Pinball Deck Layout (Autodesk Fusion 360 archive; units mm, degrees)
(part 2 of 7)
sketch "Reload Launch Plunger" plane through (0, 0, 8) normal (0, 0, 1) x axis (-1, 0, 0)
  line L1 (-360.8217, -46.399) -> (-358.0535, -46.4059)
  line L2 (-363.9178, -46.3914) -> (-361.0138, -46.3986)
  line L3 (-361.0035, -43.4046) -> (-362.4727, -43.3979)
  line L4 (-358.0433, -43.4179) -> (-360.8112, -43.4054)
  line L5 (-360.8495, -54.399) -> (-358.0816, -54.4058)
  line L6 (-363.9457, -54.3914) -> (-361.0418, -54.3985)
  line L7 (-361.0313, -51.4045) -> (-363.9352, -51.3914)
  line L8 (-358.071, -51.4179) -> (-360.8392, -51.4054)
  line L9 (-337.909, -43.4822) -> (-343.909, -43.4612)
  line L10 (-340.8631, -46.4708) -> (-337.92, -46.4822)
  line L11 (-343.8396, -46.4594) -> (-340.9768, -46.4704)
  line L12 (-343.9473, -54.4612) -> (-337.9474, -54.4821)
  line L13 (-341.0041, -51.4729) -> (-343.9361, -51.4612)
  line L14 (-338.0323, -51.4848) -> (-340.8681, -51.4735)
  line L15 (-332.4666, -38.0012) -> (-332.3898, -38.0014)
  line L16 (-332.4666, -35.9861) -> (-332.4666, -38.0012)
  line L17 (-369.4666, -35.9861) -> (-332.4666, -35.9861)
  line L18 (-369.4666, -62.0013) -> (-369.4666, -35.9861)
  line L19 (-332.4666, -62.0013) -> (-369.4666, -62.0013)
  line L20 (-332.4666, -60.0013) -> (-332.4666, -62.0013)
  line L21 (-332.3898, -38.0014) -> (-332.4666, -60.0013)
  line L22 (-369.5336, -53.1093) -> (-390.5336, -53.1093)
  line L23 (-390.5336, -45.1093) -> (-369.5336, -45.1093)
  line L24 (-371.5336, -45.1093) -> (-390.5336, -45.1093)
  line L25 (-384.5336, -45.1093) -> (-384.5336, -53.1093)
  line L26 (-387.5336, -45.1093) -> (-387.5336, -53.1093)
  line L27 (-371.5336, -45.1093) -> (-371.5336, -53.1093)
  line L28 (-384.5336, -45.1093) -> (-384.5336, -53.1093)
  line L29 (-390.5336, -53.1093) -> (-390.5336, -45.1093)
  line L30 (-369.5336, -45.1093) -> (-369.5336, -53.1093)
  line L31 (-371.5336, -53.1093) -> (-390.5336, -53.1093)
  line L32 (-332.4666, -35.9861) -> (-332.4666, -38.0012)
  line L33 (-361.0035, -43.4046) -> (-362.68, -43.397)
  line L34 (-332.4666, -38.0012) -> (-332.3898, -38.0014)
  line L35 (-358.071, -51.4179) -> (-360.8392, -51.4054)
  line L36 (-338.0323, -51.4848) -> (-340.8681, -51.4735)
  line L37 (-361.0313, -51.4045) -> (-363.9352, -51.3914)
  line L38 (-387.5336, -45.1093) -> (-387.5336, -53.1093)
  line L39 (-369.5336, -53.1093) -> (-390.5336, -53.1093)
  line L40 (-390.5336, -53.1093) -> (-390.5336, -45.1093)
  line L41 (-360.8217, -46.399) -> (-358.0535, -46.4059)
  line L42 (-337.909, -43.4822) -> (-343.909, -43.4612)
  line L43 (-332.4666, -62.0013) -> (-369.4666, -62.0013)
  line L44 (-369.4666, -35.9861) -> (-332.4666, -35.9861)
  line L45 (-332.3898, -38.0014) -> (-332.4666, -60.0013)
  line L46 (-360.8495, -54.399) -> (-358.0816, -54.4058)
  line L47 (-343.9473, -54.4612) -> (-337.9474, -54.4821)
  line L48 (-340.8631, -46.4708) -> (-337.92, -46.4822)
  line L49 (-369.4666, -62.0013) -> (-369.4666, -35.9861)
  line L50 (-363.9178, -46.3914) -> (-361.0138, -46.3986)
  line L51 (-358.0433, -43.4179) -> (-360.8112, -43.4054)
  line L52 (-341.0041, -51.4729) -> (-343.9361, -51.4612)
  line L53 (-363.9457, -54.3914) -> (-361.0418, -54.3985)
  line L54 (-343.8396, -46.4594) -> (-340.9768, -46.4704)
  line L55 (-332.4666, -60.0013) -> (-332.4666, -62.0013)
  line L56 (-387.5336, -45.1093) -> (-387.5336, -53.1093)
  line L57 (-384.5336, -45.1093) -> (-384.5336, -53.1093)
  line L58 (-371.5336, -53.1093) -> (-390.5336, -53.1093)
  line L59 (-369.5336, -53.1093) -> (-390.5336, -53.1093)
  line L60 (-371.5336, -45.1093) -> (-371.5336, -53.1093)
  line L61 (-384.5336, -45.1093) -> (-384.5336, -53.1093)
  line L62 (-390.5336, -45.1093) -> (-369.5336, -45.1093)
  line L63 (-387.5336, -45.1093) -> (-387.5336, -53.1093)
  line L64 (-390.5336, -53.1093) -> (-390.5336, -45.1093)
  line L65 (-390.5336, -53.1093) -> (-390.5336, -45.1093)
  line L66 (-369.5336, -53.1093) -> (-390.5336, -53.1093)
  line L67 (-371.5336, -45.1093) -> (-390.5336, -45.1093)
  line L68 (-418, -48.8509) -> (-390.6679, -48.8509)
  arc A1 centre (-360.9141, -44.9019) radius 1.5 clockwise from (-360.8217, -46.399) to (-361.0138, -46.3986)
  arc A2 centre (-363.9141, -44.8914) radius 1.5 clockwise from (-363.9178, -46.3914) to (-365.3912, -44.6308)
  arc A3 centre (-364.4071, -42.8897) radius 2 clockwise from (-365.3912, -44.6308) to (-362.4727, -43.3979)
  arc A4 centre (-360.9141, -44.9019) radius 1.5 clockwise from (-361.0035, -43.4046) to (-360.8112, -43.4054)
  arc A5 centre (-357.9141, -44.9124) radius 1.5 clockwise from (-358.0433, -43.4179) to (-358.0535, -46.4059)
  arc A6 centre (-357.942, -52.9123) radius 1.5 clockwise from (-358.071, -51.4179) to (-358.0816, -54.4058)
  arc A7 centre (-360.942, -52.9018) radius 1.5 clockwise from (-360.8495, -54.399) to (-361.0418, -54.3985)
  arc A8 centre (-363.942, -52.8914) radius 1.5 clockwise from (-363.9457, -54.3914) to (-363.9352, -51.3914)
  arc A9 centre (-360.942, -52.9018) radius 1.5 clockwise from (-361.0313, -51.4045) to (-360.8392, -51.4054)
  circle C1 centre (-348.9491, -54.9437) radius 2
  arc A10 centre (-343.9142, -44.9612) radius 1.5 clockwise from (-343.8396, -46.4594) to (-343.909, -43.4612)
  arc A11 centre (-337.9142, -44.9822) radius 1.5 clockwise from (-337.909, -43.4822) to (-337.92, -46.4822)
  arc A12 centre (-340.9142, -44.9717) radius 1.5 clockwise from (-340.8631, -46.4708) to (-340.9768, -46.4704)
  arc A13 centre (-343.9421, -52.9612) radius 1.5 clockwise from (-343.9473, -54.4612) to (-343.9361, -51.4612)
  arc A14 centre (-340.9421, -52.9717) radius 1.5 clockwise from (-341.0041, -51.4729) to (-340.8681, -51.4735)
  arc A15 centre (-337.9421, -52.9821) radius 1.5 clockwise from (-338.0323, -51.4848) to (-337.9474, -54.4821)
  arc A16 centre (-340.9142, -44.9717) radius 1.5 clockwise from (-340.8631, -46.4708) to (-340.9768, -46.4704)
  circle C2 centre (-348.9491, -54.9437) radius 1.8
  arc A17 centre (-343.9421, -52.9612) radius 1.5 clockwise from (-343.9473, -54.4612) to (-343.9361, -51.4612)
  arc A18 centre (-360.9141, -44.9019) radius 1.5 clockwise from (-360.8217, -46.399) to (-361.0138, -46.3986)
  arc A19 centre (-340.9421, -52.9717) radius 1.5 clockwise from (-341.0041, -51.4729) to (-340.8681, -51.4735)
  arc A20 centre (-360.942, -52.9018) radius 1.5 clockwise from (-361.0313, -51.4045) to (-360.8392, -51.4054)
  arc A21 centre (-364.4071, -42.8897) radius 1.8 clockwise from (-365.3409, -44.4285) to (-362.68, -43.397)
  arc A22 centre (-360.9141, -44.9019) radius 1.5 clockwise from (-361.0035, -43.4046) to (-360.8112, -43.4054)
  arc A23 centre (-360.942, -52.9018) radius 1.5 clockwise from (-360.8495, -54.399) to (-361.0418, -54.3985)
  arc A24 centre (-357.9141, -44.9124) radius 1.5 clockwise from (-358.0433, -43.4179) to (-358.0535, -46.4059)
  arc A25 centre (-337.9421, -52.9821) radius 1.5 clockwise from (-338.0323, -51.4848) to (-337.9474, -54.4821)
  arc A26 centre (-363.9141, -44.8914) radius 1.5 clockwise from (-363.9178, -46.3914) to (-365.3409, -44.4285)
  arc A27 centre (-363.942, -52.8914) radius 1.5 clockwise from (-363.9457, -54.3914) to (-363.9352, -51.3914)
  arc A28 centre (-357.942, -52.9123) radius 1.5 clockwise from (-358.071, -51.4179) to (-358.0816, -54.4058)
  arc A29 centre (-343.9142, -44.9612) radius 1.5 clockwise from (-343.8396, -46.4594) to (-343.909, -43.4612)
  arc A30 centre (-337.9142, -44.9822) radius 1.5 clockwise from (-337.909, -43.4822) to (-337.92, -46.4822)
  point P59 (-390.5336, -45.1093)
  point P68 (-390.5336, -45.1093)
  point P58 (-390.5336, -53.1093)
  point P70 (-390.5336, -53.1093)
  point P64 (-390.5336, -45.1093)
  point P55 (-387.5336, -53.1093)
  point P63 (-387.5336, -53.1093)
  point P54 (-387.5336, -45.1093)
  point P67 (-387.5336, -45.1093)
  point P56 (-384.5336, -53.1093)
  point P72 (-384.5336, -53.1093)
  point P57 (-384.5336, -45.1093)
  point P65 (-384.5336, -45.1093)
  point P135 (-390.5336, -45.1093)
  point P144 (-390.5336, -45.1093)
  point P134 (-390.5336, -53.1093)
  point P146 (-390.5336, -53.1093)
  point P140 (-390.5336, -45.1093)
  point P131 (-387.5336, -53.1093)
  point P139 (-387.5336, -53.1093)
  point P130 (-387.5336, -45.1093)
  point P143 (-387.5336, -45.1093)
  point P132 (-384.5336, -53.1093)
  point P148 (-384.5336, -53.1093)
  point P133 (-384.5336, -45.1093)
  point P141 (-384.5336, -45.1093)
  point P129 (-390.6679, -48.8509)
  point P154 (-390.6679, -48.8509)
  coincident P59 P68
  coincident P58 P70
  perpendicular L29 L31
  perpendicular L22 L27
  coincident P59 P64
  perpendicular L24 L27
  coincident P55 P63
  coincident P54 P67
  coincident P56 P72
  coincident P57 P65
  coincident P135 P144
  coincident P134 P146
  perpendicular L58 L65
  perpendicular L59 L60
  coincident P135 P140
  perpendicular L60 L67
  coincident P131 P139
  coincident P130 P143
  coincident P132 P148
  coincident P133 P141
  coincident P129 P154
  perpendicular L29 L68
extrude "Extrude19" new body sketch "Reload Launch Plunger" profile of L1 A1 L2 A2 A3 L3 A4 L4 A5 A6 L5 A7 L6 A8 L7 A9 L8 C1 A10 L9 A11 L10 A12 L11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 along normal blind 22 bodies "Z Reload Plunger"
sketch "Reload Launch Solenoid Plunger" plane through (369.4666, 0, 0) normal (1, 0, 0) x axis (0, 1, 0)
  line L1 (62.0013, 8) -> (35.9861, 8)
  line L2 (62.0013, 30) -> (62.0013, 8)
  line L3 (35.9861, 30) -> (62.0013, 30)
  line L4 (35.9861, 8) -> (35.9861, 30)
  circle C1 centre (48.9937, 19) radius 4
  dimension "d134" diameter C1 = 8
extrude "Extrude20" add sketch "Reload Launch Solenoid Plunger" profile of C1 along normal blind 21
extrude "Extrude21" cut sketch "Bottom Runways" along normal blind 30
extrude "Extrude22" cut sketch "Bottom Runways" blind 30 from offset 6
extrude "Extrude23" cut sketch "Bottom Runways" along normal blind 30
extrude "Extrude24" cut sketch "Bottom Runways" blind 30 from offset 6
extrude "Extrude25" cut sketch "Bottom Runways" along normal blind 30
extrude "Extrude26" cut sketch "Bottom Runways" blind 30 from offset 6
work_axis "WorkAxis1"
extrude "Extrude27" new body sketch "Bottom Runways" blind 1.2 from offset 4.1 bodies "Reload Ball Release Lower Washer"
extrude "Extrude28" add sketch "Bottom Runways" along normal blind 25.6
extrude "Extrude29" add sketch "Bottom Runways" along normal blind 15
extrude "Extrude30" new body sketch "Bottom Runways" blind 13.5 from offset 5.5 bodies "Reload Ball Release Drive"
extrude "Extrude31" add sketch "Bottom Runways" blind 6 from offset 19
extrude "Extrude32" add sketch "Bottom Runways" blind 7.8 from offset 19
sketch "Reload Solenoid Coupling Arm" plane through (0, 0, 19) normal (0, 0, 1) x axis (-1, 0, 0)
  line L1 (-444.88, -53.4852) -> (-387.5956, -53.8589)
  line L2 (-423.127, -44.127) -> (-387.5336, -44.3593)
  line L3 (-398, -53.791) -> (-398, -44.291)
  line L4 (-395, -53.8106) -> (-395, -44.3106)
  line L5 (-440.9582, -46.0106) -> (-425.114, -46.114)
  line L6 (-425.114, -46.114) -> (-423.127, -44.127)
  line L7 (-451, -44) -> (-451, -57.3866)
  line L8 (-451, -44) -> (-446, -39)
  line L9 (-435.7954, -39) -> (-446, -39)
  line L10 (-457.6104, -58.2381) -> (-457.6104, -37.3896)
  line L11 (-447.333, -53.4692) -> (-444.88, -53.4852)
  line L12 (-442.7019, -50) -> (-449.7621, -50)
  line L13 (-384.6635, -53.878) -> (-383.3324, -51.2655)
  line L14 (-384.6635, -53.878) -> (-387.5956, -53.8589)
  line L15 (-444.88, -53.4852) -> (-447.333, -53.4692)
  line L16 (-446.1065, -53.4772) -> (-447.333, -53.4692)
  line L17 (-447.333, -53.4692) -> (-447.9394, -53.4652)
  line L18 (-437.9654, -48.7353) -> (-444.849, -48.7353)
  line L19 (-448.2234, -45.3921) -> (-448.2078, -45.3765)
  line L20 (-457.6104, -34.8442) -> (-453.3534, -30.5668)
  line L21 (-457.6104, -34.8442) -> (-457.6104, -37.3896)
  line L22 (-440.0563, -35.1519) -> (-448.7462, -35.1519)
  line L23 (-446.8964, -30.0697) -> (-446.8096, -29.831)
  circle C1 centre (-444.849, -48.7353) radius 3
  circle C2 centre (-444.849, -48.7353) radius 3.3
  circle C3 centre (-387.5336, -49.1093) radius 1.8
  arc A1 centre (-387.5646, -49.1091) radius 4.7499 clockwise from (-387.5336, -44.3593) to (-383.3324, -51.2655)
  arc A2 centre (-440, -40) radius 15.75 clockwise from (-452.1681, -30) to (-442.002, -24.3778)
  arc A3 centre (-448.7462, -35.1519) radius 4.75 clockwise from (-444.8545, -32.4285) to (-446.0894, -39.0894)
  circle C4 centre (-448.7462, -35.1519) radius 3.25
  circle C5 centre (-453.7462, -62.1519) radius 3.75
  arc A4 centre (-453.7462, -62.1519) radius 5.5 clockwise from (-451, -57.3866) to (-457.6104, -58.2381)
  arc A5 centre (-444.849, -48.7353) radius 5.65 clockwise from (-447.9394, -53.4652) to (-449.6099, -45.6928)
  arc A6 centre (-444.8491, -48.7353) radius 4.75 clockwise from (-448.2078, -45.3765) to (-440.9582, -46.0106)
  arc A7 centre (-448.7673, -46.2313) radius 1 clockwise from (-449.6099, -45.6928) to (-448.2234, -45.3921)
  arc A8 centre (-448.7462, -35.1519) radius 6.5 clockwise from (-453.3534, -30.5668) to (-447.6707, -28.7415)
  arc A9 centre (-448.7462, -35.1519) radius 4.75 clockwise from (-446.3701, -31.0389) to (-444.8545, -32.4285)
  arc A10 centre (-447.8361, -29.7277) radius 1 clockwise from (-447.6707, -28.7415) to (-446.8964, -30.0697)
  arc A11 centre (-445.8699, -30.173) radius 1 clockwise from (-446.3701, -31.0389) to (-446.8096, -29.831)
  point P7 (-387.5956, -53.8589)
  point P10 (-398, -53.791)
  point P11 (-398, -44.291)
  point P12 (-395, -53.8106)
  point P13 (-395, -44.3106)
  point P17 (-448.7462, -35.1519)
  point P18 (-448.7462, -35.1519)
  point P27 (-446.0894, -39.0894)
  point P19 (-453.7462, -62.1519)
  point P29 (-453.7462, -62.1519)
  point P3 (-444.849, -48.7353)
  point P42 (-444.849, -48.7353)
  point P52 (-448.7462, -35.1519)
  point P28 (-448.7462, -35.1519)
  point P54 (-448.7462, -35.1519)
  coincident P7 A1
  vertical L3
  coincident L1 P10
  coincident L2 P11
  vertical L4
  coincident L1 P12
  coincident L2 P13
  coincident P17 P18
  vertical L7
  horizontal L9
  vertical L10
  coincident L8 P27
  concentric A3 C4
  coincident P19 P29
  concentric C5 A4
  tangent L1 A6
  tangent L1 A1
  tangent L11 A6
  horizontal L12
  tangent A1 L13
  tangent A1 L14
  concentric C1 A5
  parallel L11 L15
  parallel L1 L16
  parallel L16 L17
  horizontal L18
  coincident P3 P42
  tangent A5 A7
  tangent A6 L19
  concentric A3 A8
  tangent A8 L20
  parallel L10 L21
  horizontal L22
  coincident P18 P52
  coincident P28 P54
  tangent A8 A10
  tangent L23 A10
  tangent A9 A11
  tangent L23 A11
  dimension "d319" diameter A5 = 11.3
  dimension "d321" radius A7 = 1
  dimension "d338" radius A10 = 1
  dimension "d339" radius A11 = 1
extrude "Extrude33" new body sketch "Reload Solenoid Coupling Arm" profile of C2 A6 L1 L2 L3 L5 L6 blind 7.1 from offset 0.3 bodies "Reload Ball Release Solenoid Coupling"
extrude "Extrude34" add sketch "Reload Solenoid Coupling Arm" profile of L1 L2 L3 L4 along normal blind 7.4 and against normal blind 7.3
extrude "Extrude35" add sketch "Reload Solenoid Coupling Arm" profile of C3 A1 L1 L2 L4 blind 3 from offset 4.4
extrude "Extrude36" add sketch "Reload Solenoid Coupling Arm" profile of C3 A1 L1 L2 L4 blind -3 from offset -4.3
extrude "Extrude37" new body sketch "Bottom Runways" blind 15.5 from offset 3.2 bodies "Reload Ball Release Slide"
extrude "Extrude38" add sketch "Bottom Runways" blind 8.1 from offset 18.7
extrude "Extrude39" new body sketch "Reload Solenoid Coupling Arm" profile of A3 L7 L8 L10 C4 C5 A4 blind 7.1 from offset 0.3 bodies "Reload Ball Release Slide Coupling"
extrude "Extrude40" add sketch "Bottom Runways" blind 15 from offset 18.7
extrude "Extrude41" add sketch "Bottom Runways" blind 7.3 from offset 26.4
extrude "Extrude42" new body sketch "Bottom Runways" profile of L29 L30 L31 L37 L38 blind 27.6 from offset 3.1
chamfer "Chamfer1" distance 3 distance 1.2
fillet "Fillet3" radius 3
fillet "Fillet5" radius 2
sketch "Front panel Plunger" plane through (0, 0, 0) normal (0, -1, 0) x axis (1, 0, 0)
  line L1 (500, 25) -> (500, 0)
  line L2 (475.0152, 0) -> (465, 0)
  line L3 (475.0759, 0) -> (475.0759, 25)
  line L4 (500, 0) -> (475.0759, 0)
  line L5 (500, 0) -> (500, 25)
  line L6 (475.0759, 25) -> (500, 25)
  circle C1 centre (487.5, 12.5) radius 8
  circle C2 centre (495.5, 20.5) radius 1.75
  circle C3 centre (479.5, 20.5) radius 1.75
  circle C4 centre (495.5, 4.5) radius 1.75
  circle C5 centre (479.5, 4.5) radius 1.75
  point P9 (475.0759, 25)
  point P13 (475.0759, 25)
  point P10 (475.0759, 0)
  point P14 (475.0759, 0)
  point P2 (500, 0)
  point P15 (500, 0)
  point P3 (500, 25)
  point P16 (500, 25)
  point P17 (500, 25)
  point P18 (475.0759, 25)
  coincident P9 P13
  coincident P10 P14
  coincident P2 P15
  coincident P3 P16
  coincident P3 P17
  coincident P9 P18
  dimension "d913" diameter C1 = 16
extrude "Extrude43" cut sketch "Front panel Plunger" profile of C1 against normal blind 12
work_plane "WorkPlane1" AlongDistance 10
extrude "Extrude45" add sketch "Reload Plunger" profile of L1 L4 L6 L13 L16 L17 L18 L21 L22 L23 L24 L25 L26 A1 L27 A2 A3 A4 C1 L28 L29 L30 L31 L32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 blind 4 from offset 3
extrude "Extrude46" cut sketch "Reload Plunger" profile of L17 A1 L27 A2 A3 A4 C1 L32 L33 A5 C2 L34 A6 C3 C4 L36 A7 A8 A9 A10 A11 A12 L40 C5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 along normal blind 100
extrude "Extrude47" cut sketch "Reload Plunger" profile of A1 L27 A2 A3 C1 L32 L33 C2 L34 C3 C4 L36 A7 L40 C5 L41 C6 A13 C7 C8 L43 L44 C9 L45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 along normal blind 4 bodies "Left Loweer Deck Section (1)"
extrude "Extrude48" new body sketch "Reload Plunger" profile of L1 L4 L6 L13 L16 L17 L18 L21 L22 L23 L24 L25 L26 A1 L27 A2 A3 A4 C1 L28 L29 L30 L31 L32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 blind 22 from offset 7.1 bodies "Reload Solenoid"
sketch "Sketch17" plane through (107.1589, 52.7287, 0) normal (0.8973, 0.4415, 0) x axis (-0.4415, 0.8973, 0)
  line L1 (-0.1972, 7.1) -> (-26.2124, 7.1)
  line L2 (-0.1972, 29.1) -> (-0.1972, 7.1)
  line L3 (-26.2124, 29.1) -> (-0.1972, 29.1)
  line L4 (-26.2124, 7.1) -> (-26.2124, 29.1)
  circle C1 centre (-13.2048, 18.1) radius 4
  dimension "d246" diameter C1 = 8
extrude "Extrude49" add sketch "Sketch17" profile of C1 along normal blind 21
extrude "Extrude51" new body sketch "Reload Flipper" profile of C1 A1 A2 C2 A3 L2 L3 L4 C3 L5 A4 L6 A5 A6 A7 L7 blind 8 from offset 8.2 bodies "Reload Load Flipper"
work_axis "WorkAxis3"
extrude "Extrude52" new body sketch "reload coupling" profile of L1 L2 L5 L6 L7 L8 L9 L10 L12 blind 8 from offset 14.1 bodies "Reload Load Coupling"
extrude "Extrude53" new body sketch "reload coupling" profile of L1 L2 L3 L4 C1 A1 A2 L10 L12 blind 3 from offset 10.7
extrude "Extrude54" add sketch "reload coupling" profile of L1 L2 L10 L12 blind 5 from offset 10.7
extrude "Extrude55" new body sketch "reload coupling" profile of L1 L2 L3 L4 C1 A1 A2 L10 L12 blind 3 from offset 22.4
extrude "Extrude56" add sketch "reload coupling" profile of L1 L2 L10 L12 blind 1 from offset 22
extrude "Extrude57" add sketch "reload coupling" profile of A3 L1 L2 C2 L5 L6 L7 L8 L9 blind 5.7 from offset 16.4
chamfer "Chamfer3" distance 2 distance 2
chamfer "Chamfer5" distance 38 distance 2.6
move "Move10"
move "Move11"
sketch "Reload Launch Retainer" plane through (0, 0, 17) normal (0, 0, 1) x axis (-1, 0, 0)
  circle C1 centre (-185.8525, -49.8361) radius 1.4
  circle C2 centre (-185.8525, -49.8361) radius 10
  circle C3 centre (-185.8525, -49.8361) radius 1.75
  concentric C1 C2
  concentric C2 C3
  dimension "d282" diameter C1 = 2.8
  dimension "d283" diameter C2 = 20
  dimension "d284" diameter C3 = 3.5
extrude "Extrude58" cut sketch "Reload Launch Retainer" profile of C1 against normal blind 12
extrude "Extrude59" new body sketch "Reload Launch Retainer" profile of C2 C3 blind 2 from offset 0.2 bodies "Reload Load Retaining Washer"
extrude "Extrude60" cut sketch "Bottom Runways" along normal blind 10
sketch "Sketch19" plane through (0, 0, 0) normal (1, 0, 0) x axis (0, 1, 0)
extrude "Extrude61" cut sketch "Bottom Runways" along normal blind 10
sketch "Reload Ball Release Slide Gusset" plane through (0, 0, 33.7) normal (0, 0, 1) x axis (-1, 0, 0)
  line L1 (-437.4865, -56.1294) -> (-437.4865, -121.6401)
  line L2 (-441.9908, -73.2037) -> (-441.9908, -56.2022)
  line L3 (-441.9885, -121.6401) -> (-441.9885, -83.2046)
  line L4 (-441.9885, -121.6401) -> (-437.4865, -121.6401)
  line L5 (-441.9908, -56.2022) -> (-441.9885, -121.6401)
  line L6 (-437.4865, -56.1294) -> (-437.4865, -121.6401)
  line L7 (-441.9908, -56.2022) -> (-437.4865, -56.1294)
  line L8 (-444.1098, -119.5188) -> (-441.9885, -121.6401)
  line L9 (-411.5261, -121.6401) -> (-441.9885, -121.6401)
  line L10 (-435.3652, -119.5188) -> (-437.4865, -121.6401)
  line L11 (-367.2232, -121.6401) -> (-437.4865, -121.6401)
  line L12 (-437.4865, -56.1294) -> (-435.3652, -58.2507)
  line L13 (-441.9908, -56.2022) -> (-444.1121, -58.3235)
  line L14 (-444.1098, -119.5188) -> (-444.1121, -58.3235)
  line L15 (-435.3652, -119.5188) -> (-435.3652, -58.2507)
  line L16 (-441.9885, -83.2046) -> (-441.9908, -73.2037)
  line L17 (-437.4865, -121.6401) -> (-441.9885, -121.6401)
  arc A1 centre (-440, -40) radius 16.3241 clockwise from (-437.4865, -56.1294) to (-441.9908, -56.2022)
  point P2 (-437.4865, -121.6401)
  point P9 (-437.4865, -121.6401)
  point P8 (-441.9885, -121.6401)
  point P10 (-441.9885, -121.6401)
  point P4 (-441.9908, -56.2022)
  point P11 (-441.9908, -56.2022)
  point P12 (-437.4865, -121.6401)
  point P3 (-437.4865, -56.1294)
  point P13 (-437.4865, -56.1294)
  coincident P2 P9
  coincident P8 P10
  coincident P4 P11
  coincident P2 P12
  coincident P3 P13
  horizontal L9
  horizontal L11
  parallel L6 L15
combine "Combine3" bodies "Reload Ball Release Slide (1)", "Reload Ball Release Slide Coupling"
extrude "Extrude63" add sketch "Bottom Runways" blind 26.7 from offset 3.1
fillet "Fillet8" radius 1.2
combine "Combine4"
fillet "Fillet9" radius 1.2
fillet "Fillet10" radius 2
extrude "Extrude64" add sketch "Bottom Runways" blind 4.7 from offset 29
fillet "Fillet14" radius 1.4
extrude "Extrude65" cut sketch "Front panel Plunger" profile of C2 C3 C4 C5 against normal blind 20
chamfer "Chamfer8" distance 70
chamfer "Chamfer9" distance 3.3 distance 3.3
sketch "Reload Washers" plane through (0, 0, 26.8) normal (0, 0, 1) x axis (-1, 0, 0)
  circle C1 centre (-453.7462, -62.1519) radius 1.4
  circle C2 centre (-453.7462, -62.1519) radius 4.75
  circle C3 centre (-453.7462, -62.1519) radius 1.9
  concentric C1 C2
  concentric C2 C3
extrude "Extrude66" new body sketch "Reload Washers" profile of C2 C3 blind 1.5 from offset 0.1 bodies "Reload Ball Release Washer"
sketch "Top Runways" plane through (0, 0, 0) normal (0, 0, 1) x axis (1, 0, 0)
  line L1 (418.7386, 900) -> (350, 900)
  line L2 (500, 818.7386) -> (500, 750)
  line L3 (196.0012, 571.9864) -> (254.0012, 571.9875)
  line L4 (196.0105, 607.9864) -> (254.0105, 607.9874)
  line L5 (208.4571, 607.9866) -> (208.4571, 607.9865)
  line L6 (196.0012, 571.9864) -> (196.0105, 607.9864)
  line L7 (254.0012, 571.9875) -> (254.0105, 607.9874)
  line L8 (284.0012, 681.9875) -> (284.0105, 717.9874)
  line L9 (226.0012, 681.9864) -> (284.0012, 681.9875)
  line L10 (238.4571, 717.9866) -> (238.4571, 717.9865)
  line L11 (226.0012, 681.9864) -> (226.0105, 717.9864)
  line L12 (226.0105, 717.9864) -> (284.0105, 717.9874)
  line L13 (121.013, 717.9864) -> (179.0105, 717.9874)
  line L14 (121.0038, 681.9864) -> (179.0012, 681.9875)
  line L15 (133.4571, 717.9866) -> (133.4571, 717.9865)
  line L16 (121.0012, 671.9864) -> (121.013, 717.9864)
  line L17 (179.0012, 681.9875) -> (179.0105, 717.9874)
  line L18 (30, 751.0007) -> (96.5, 751)
  line L19 (30, 899) -> (30, 751.0007)
  line L20 (30, 899) -> (175, 899)
  curve K1 (96.5, 751) -> (175, 899)
  line L21 (500, 640) -> (500, 900)
  line L22 (599.1154, 640) -> (500, 640)
  line L23 (337.9325, 758.8476) -> (336, 760)
  line L24 (65, 808.3604) -> (65, 750)
  line L25 (88.7119, 875) -> (88.7119, 844)
  line L26 (30, 750) -> (96.5068, 750)
  line L27 (40, 751.0006) -> (40, 808.3604)
  line L28 (88.7119, 875.3) -> (88.7119, 875)
  line L29 (114.9928, 875.3) -> (88.7119, 875.3)
  line L30 (88.7119, 843.7) -> (88.7119, 844)
  line L31 (93.2563, 843.7) -> (88.7119, 843.7)
  line L32 (30, 532) -> (30, 200)
  line L33 (260, 844) -> (250, 844)
  line L34 (240, 844) -> (250, 844)
  line L35 (240, 843.6) -> (250, 843.6)
  line L36 (260, 843.6) -> (250, 843.6)
  line L37 (240, 875.4) -> (250, 875.4)
  line L38 (260, 875.4) -> (250, 875.4)
  line L39 (240, 875) -> (250, 875)
  line L40 (260, 875) -> (250, 875)
  line L41 (240, 877.8) -> (250, 877.8)
  line L42 (260, 877.8) -> (250, 877.8)
  line L43 (240, 841.2) -> (250, 841.2)
  line L44 (260, 841.2) -> (250, 841.2)
  line L45 (260, 877.8) -> (260, 841.2)
  line L46 (240, 877.8) -> (240, 841.2)
  line L47 (240, 844.8) -> (250, 844.8)
  line L48 (260, 844.8) -> (250, 844.8)
  line L49 (240, 874.2) -> (250, 874.2)
  line L50 (260, 874.2) -> (250, 874.2)
  line L51 (356.5976, 855.5288) -> (339.7285, 829.4709)
  line L52 (356.9976, 855.5288) -> (340, 829.2724)
  line L53 (356.7139, 855.7084) -> (356.5976, 855.5288)
  line L54 (339.7285, 829.4709) -> (340, 829.2724)
  line L55 (356.7139, 855.7084) -> (356.9976, 855.5288)
  line L56 (348.3194, 861.1427) -> (331.6559, 835.3728)
  line L57 (348.5367, 861.4785) -> (348.3194, 861.1427)
  line L58 (357.215, 855.8645) -> (356.9976, 855.5288)
  line L59 (331.6559, 835.3728) -> (331.4385, 835.037)
  line L60 (339.7639, 828.9495) -> (340, 829.2724)
  line L61 (349.5598, 863.0599) -> (348.5367, 861.4785)
  line L62 (358.5186, 857.8797) -> (357.215, 855.8645)
  line L63 (347.885, 860.4709) -> (347.8846, 860.4712)
  line L64 (332.0896, 836.0435) -> (332.1281, 836.0186)
  line L65 (330.1343, 833.0224) -> (331.4385, 835.037)
  line L66 (338.3473, 827.0121) -> (339.7639, 828.9495)
  line L67 (329.5524, 832.2273) -> (330.1343, 833.0224)
  line L68 (342.5446, 824.295) -> (338.3473, 827.0121)
  line L69 (362.5553, 855.2057) -> (342.5446, 824.295)
  line L70 (343.6876, 826.0605) -> (339.7639, 828.9495)
  line L71 (361.302, 853.2698) -> (357.215, 855.8645)
  line L72 (260, 859.5) -> (240, 859.5)
  line L73 (260, 867) -> (240, 867)
  line L74 (260, 852) -> (240, 852)
  line L75 (30, 903.7) -> (30, 899)
  line L76 (205.1463, 903.7) -> (30, 903.7)
  line L77 (205.1463, 903.7) -> (175, 899)
  line L78 (412.2668, 902.8) -> (350, 902.8)
  line L79 (303.8002, 902.8) -> (350, 902.8)
  line L80 (303.8002, 902.8) -> (350, 900)
  circle C1 centre (438.5624, 880.2435) radius 2
  arc A1 centre (350, 750) radius 150 clockwise from (350, 900) to (500, 750)
  circle C2 centre (492.7435, 816.5624) radius 5
  circle C3 centre (492.7435, 816.5624) radius 2
  circle C4 centre (438.5624, 880.2435) radius 5
  arc A2 centre (350, 750) radius 165 clockwise from (418.7386, 900) to (500, 818.7386)
  circle C5 centre (250, 810) radius 2.25
  circle C6 centre (250, 770) radius 2.25
  circle C7 centre (293, 770) radius 2.25
  circle C8 centre (293, 810) radius 2.25
  circle C9 centre (207, 770) radius 2.25
  circle C10 centre (164, 770) radius 2.25
  circle C11 centre (164, 810) radius 2.25
  circle C12 centre (207, 810) radius 2.25
  circle C13 centre (255, 700) radius 42.5
  circle C14 centre (150, 700) radius 42.5
  circle C15 centre (225, 590) radius 42.5
  circle C16 centre (202.0148, 603.9876) radius 1.75
  circle C17 centre (202.0148, 575.9876) radius 1.75
  circle C18 centre (248.0148, 603.9876) radius 1.75
  circle C19 centre (248.0148, 575.9876) radius 1.75
  circle C20 centre (232.0148, 685.9876) radius 1.75
  circle C21 centre (278.0148, 713.9876) radius 1.75
  circle C22 centre (232.0148, 713.9876) radius 1.75
  circle C23 centre (278.0148, 685.9876) radius 1.75
  circle C24 centre (127.0148, 703.9876) radius 1.75
  circle C25 centre (173.0148, 685.9876) radius 1.75
  circle C26 centre (173.0148, 713.9876) radius 1.75
  circle C27 centre (127.0148, 675.9876) radius 1.75
  circle C28 centre (255, 700) radius 13
  circle C29 centre (150, 700) radius 13
  circle C30 centre (225, 590) radius 13
  circle C31 centre (35, 759) radius 4
  circle C32 centre (35, 759) radius 2.25
  circle C33 centre (45, 890) radius 2.25
  circle C34 centre (45, 890) radius 4
  circle C35 centre (115, 890) radius 4
  circle C36 centre (115, 890) radius 2.25
  circle C37 centre (293, 770) radius 12
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  point P4 (350, 750)
  point P5 (350, 750)
  point P29 (196.0012, 571.9864)
  point P27 (254.0012, 571.9875)
  point P28 (208.4571, 607.9866)
  point P36 (226.0012, 681.9864)
  point P37 (284.0012, 681.9875)
  point P38 (238.4571, 717.9866)
  point P50 (121.0038, 681.9864)
  point P54 (179.0012, 681.9875)
  point P52 (133.4571, 717.9866)
  point P102 (65, 750)
  point P101 (103.6396, 808.3604)
  point P106 (103.6396, 808.3604)
  point P110 (40, 751.0006)
  point P112 (114.9928, 875.3)
  point P114 (93.2563, 843.7)
  point P124 (250, 844)
  point P131 (250, 844)
  point P165 (356.9976, 855.5288)
  point P170 (356.9976, 855.5288)
  point P181 (332.0896, 836.0435)
  point P204 (331.5475, 835.2055)
  point P205 (331.1121, 834.5328)
  point P206 (330.8966, 834.1999)
  point P209 (356.5629, 854.8572)
  point P210 (347.885, 860.4709)
  point P211 (348.2561, 861.0449)
  point P212 (348.0389, 860.709)
  point P213 (347.6045, 860.0373)
  point P226 (343.6876, 826.0605)
  point P227 (361.302, 853.2698)
  point P228 (240, 859.5)
  point P229 (260, 859.5)
  point P139 (260, 875.4)
  point P142 (260, 875)
  point P162 (260, 874.2)
  point P231 (260, 867)
  point P232 (260, 852)
  point P155 (260, 844.8)
  point P133 (260, 843.6)
  point P130 (260, 844)
  point P132 (240, 844)
  point P135 (240, 843.6)
  point P157 (240, 844.8)
  point P233 (240, 852)
  point P230 (240, 867)
  point P160 (240, 874.2)
  point P141 (240, 875)
  point P137 (240, 875.4)
  point P238 (350, 750)
  coincident P4 P5
  coincident P29 L6
  coincident P27 L3
  coincident P28 L4
  coincident P36 L11
  coincident P37 L9
  coincident P38 L12
  coincident P50 L16
  coincident P54 L14
  coincident P52 L13
  concentric C13 C28
  concentric C31 C32
  concentric C33 C34
  concentric C35 C36
  parallel L2 L21
  horizontal L22
  coincident P102 L26
  coincident P101 P106
  coincident L18 P110
  vertical L27
  coincident K1 P112
  perpendicular L28 L29
  coincident K1 P114
  perpendicular L30 L31
  coincident P124 P131
  perpendicular L42 L45
  perpendicular L41 L46
  coincident P165 P170
  perpendicular L54 L60
  perpendicular L51 L63
  coincident L56 P181
  perpendicular L56 L64
  parallel L59 L65
  coincident L59 P204
  coincident L65 P205
  coincident L65 P206
  coincident L52 P209
  coincident L56 P210
  coincident L56 P211
  coincident L56 P212
  coincident L56 P213
  perpendicular L68 L69
  coincident L69 P226
  coincident L69 P227
  midpoint L46 P228
  midpoint L45 P229
  perpendicular L45 L72
  coincident P139 L45
  perpendicular L38 L45
  coincident P142 L45
  perpendicular L40 L45
  coincident L45 P162
  perpendicular L45 L50
  coincident L45 P231
  perpendicular L45 L73
  coincident L45 P232
  perpendicular L45 L74
  coincident L45 P155
  perpendicular L45 L48
  coincident P133 L45
  perpendicular L36 L45
  coincident P130 L45
  perpendicular L33 L45
  coincident P132 L46
  perpendicular L34 L46
  coincident P135 L46
  perpendicular L35 L46
  coincident L46 P157
  perpendicular L46 L47
  coincident L46 P233
  perpendicular L46 L74
  coincident L46 P230
  coincident L46 P160
  perpendicular L46 L49
  coincident P141 L46
  perpendicular L39 L46
  coincident P137 L46
  perpendicular L37 L46
  perpendicular L20 L75
  perpendicular L75 L76
  parallel L78 L79
  coincident P4 P238
  dimension "d425" diameter C5 = 4.5
  dimension "d426" diameter C6 = 4.5
  dimension "d427" diameter C8 = 4.5
  dimension "d428" diameter C7 = 4.5
  dimension "d431" diameter C11 = 4.5
  dimension "d432" diameter C10 = 4.5
  dimension "d433" diameter C12 = 4.5
  dimension "d434" diameter C9 = 4.5
  dimension "d435" diameter C13 = 85
  dimension "d436" diameter C14 = 85
  dimension "d437" diameter C15 = 85
  dimension "d536" diameter C31 = 8
  dimension "d537" diameter C32 = 4.5
  dimension "d540" diameter C34 = 8
  dimension "d541" diameter C33 = 4.5
  dimension "d542" diameter C35 = 8
  dimension "d543" diameter C36 = 4.5
  dimension "d579" diameter = 18
  dimension "d580" diameter = 18
  dimension "d583" diameter = 18
  dimension "d584" diameter = 18
  dimension "d585" diameter = 18
  dimension "d586" diameter = 18
  dimension "d587" diameter = 18
  dimension "d588" diameter = 18
  dimension "d743" diameter = 8
  dimension "d744" diameter = 4.5
  dimension "d799" diameter = 8
extrude "Extrude70" new body sketch "Top Runways" profile of L1 A1 C2 L2 C4 A2 along normal blind 25 bodies "Top Right Corner"
extrude "Extrude71" add sketch "Top Runways" profile of C1 C2 C3 C4 along normal blind 4
sketch "Side Alleys" plane through (0, 0, 0) normal (0, 0, 1) x axis (1, 0, 0)
  line L1 (428, 247.6) -> (428, 360.3398)
  line L2 (438, 225) -> (336.5156, 172.0071)
  line L3 (438, 360.3397) -> (438, 225)
  line L4 (428, 247.6) -> (325.1003, 193.868)
  line L5 (427.8841, 247.8619) -> (428, 247.6)
  line L6 (250, 300) -> (250, 150)
  line L7 (62, 360.3397) -> (62, 225)
  line L8 (72, 247.6) -> (174.8997, 193.868)
  line L9 (72, 247.6) -> (72, 360.3398)
  line L10 (72.1159, 247.8619) -> (72, 247.6)
  line L11 (62, 225) -> (163.4844, 172.0071)
  circle C1 centre (348.3539, 192.2903) radius 2.25
  circle C2 centre (433, 235) radius 2.25
  circle C3 centre (433, 350) radius 2.25
  arc A1 centre (323.2371, 178.9842) radius 15 clockwise from (325.1003, 193.868) to (336.5156, 172.0071)
  circle C4 centre (348.3539, 192.2903) radius 4
  circle C5 centre (433, 235) radius 4
  circle C6 centre (433, 350) radius 4
  arc A2 centre (433, 369) radius 10 clockwise from (438, 360.3397) to (428, 360.3398)
  circle C7 centre (151.6461, 192.2903) radius 4
  circle C8 centre (67, 350) radius 2.25
  circle C9 centre (67, 235) radius 4
  arc A3 centre (67, 369) radius 10 clockwise from (72, 360.3398) to (62, 360.3397)
  circle C10 centre (151.6461, 192.2903) radius 2.25
  arc A4 centre (176.7629, 178.9842) radius 15 clockwise from (163.4844, 172.0071) to (174.8997, 193.868)
  circle C11 centre (67, 235) radius 2.25
  circle C12 centre (67, 350) radius 4
  circle C13 centre (433, 369) radius 9
  circle C14 centre (67, 369) radius 9
  circle C15 centre (433, 369) radius 2.25
  circle C16 centre (67, 369) radius 2.25
  point P6 (438, 225)
  point P14 (438, 225)
  point P2 (438, 225)
  point P30 (62, 225)
  point P3 (428, 247.6)
  point P22 (72, 247.6)
  point P37 (62, 225)
  point P7 (325.1003, 193.868)
  point P29 (174.8997, 193.868)
  point P10 (336.5156, 172.0071)
  point P28 (163.4844, 172.0071)
  point P12 (428, 247.6)
  point P32 (72, 247.6)
  point P13 (427.8841, 247.8619)
  point P34 (72.1159, 247.8619)
  point P27 (62, 225)
  point P18 (428, 360.3398)
  point P31 (72, 360.3398)
  point P19 (438, 360.3397)
  point P26 (62, 360.3397)
  coincident P6 P14
  coincident P2 P6
  vertical L6
  symmetric P2 L6 P30
  symmetric P3 L6 P22
  symmetric P6 L6 P37
  symmetric P7 L6 P29
  symmetric P10 L6 P28
  symmetric P12 L6 P32
  symmetric P13 L6 P34
  symmetric P14 L6 P27
  symmetric C1 L6 C10
  symmetric C2 L6 C11
  symmetric C3 L6 C8
  symmetric A1 L6 A4
  symmetric C4 L6 C7
  symmetric C5 L6 C9
  symmetric C6 L6 C12
  symmetric A2 L6 A3
  symmetric P18 L6 P31
  symmetric P19 L6 P26
  concentric A2 C13
  concentric A3 C14
  concentric A2 C15
  concentric A3 C16
  dimension "d399" diameter C6 = 8
  dimension "d400" diameter C3 = 4.5
  dimension "d401" diameter C5 = 8
  dimension "d402" diameter C2 = 4.5
  dimension "d403" diameter C4 = 8
  dimension "d404" diameter C1 = 4.5
  dimension "d406" radius A2 = 10
  dimension "d467" diameter C13 = 18
  dimension "d468" diameter C14 = 18
  dimension "d470" diameter C15 = 4.5
  dimension "d471" diameter C16 = 4.5
extrude "Extrude72" new body sketch "Side Alleys" profile of L1 L2 L3 A1 C4 C5 L4 C6 A2 along normal blind 25 bodies "Outer Runway Right"
extrude "Extrude73" add sketch "Side Alleys" profile of C1 C2 C3 C4 C5 C6 along normal blind 4
fillet "Fillet19" radius 1.4
fillet "Fillet20" radius 1.4
fillet "Fillet21" radius 0.8
extrude "Extrude74" new body sketch "Side Alleys" profile of C7 C9 L7 A3 L8 L9 L11 A4 C12 along normal blind 25 bodies "Outer Runway Left"
extrude "Extrude75" add sketch "Side Alleys" profile of C7 C8 C9 C10 C11 C12 along normal blind 4
fillet "Fillet22" radius 2
fillet "Fillet23" radius 0.8
sketch "Round_For_Bumper" plane through (0, 0, 0) normal (0, 0, 1) x axis (1, 0, 0)
  line L1 (136.7259, 96.0353) -> (137.5213, 96.3248)
  line L2 (136.473, 95.4929) -> (136.7259, 96.0353)
  line L3 (137.0154, 95.2399) -> (136.473, 95.4929)
  line L4 (137.8108, 95.5294) -> (137.0154, 95.2399)
  line L5 (136.9072, 94.2999) -> (136.7625, 94.6975)
  line L6 (136.8348, 94.4987) -> (136.9072, 94.2999)
  line L7 (138.0279, 94.9329) -> (136.8348, 94.4987)
  line L8 (137.7567, 95.0594) -> (138.0279, 94.9329)
  line L9 (137.3232, 93.7757) -> (137.1243, 93.7033)
  line L10 (137.3955, 93.5769) -> (137.3232, 93.7757)
  line L11 (137.1967, 93.5045) -> (137.3955, 93.5769)
  line L12 (137.1243, 93.7033) -> (137.1967, 93.5045)
  line L13 (138.7516, 92.9445) -> (138.4804, 93.071)
  line L14 (138.8963, 92.5469) -> (138.7516, 92.9445)
  line L15 (138.7698, 92.2757) -> (138.8963, 92.5469)
  line L16 (137.9745, 91.9862) -> (138.7698, 92.2757)
  line L17 (137.7033, 92.1126) -> (137.9745, 91.9862)
  line L18 (137.5585, 92.5103) -> (137.7033, 92.1126)
  line L19 (137.685, 92.7815) -> (137.5585, 92.5103)
  line L20 (138.4804, 93.071) -> (137.685, 92.7815)
  line L21 (139.4402, 96.8205) -> (139.3137, 96.5493)
  line L22 (139.2954, 97.2181) -> (139.4402, 96.8205)
  line L23 (139.0242, 97.3446) -> (139.2954, 97.2181)
  line L24 (138.2289, 97.0551) -> (139.0242, 97.3446)
  line L25 (138.1024, 96.7839) -> (138.2289, 97.0551)
  line L26 (138.2472, 96.3862) -> (138.1024, 96.7839)
  line L27 (138.5184, 96.2598) -> (138.2472, 96.3862)
  line L28 (138.609, 95.3921) -> (138.4643, 95.7897)
  line L29 (138.5366, 95.5909) -> (138.609, 95.3921)
  line L30 (139.332, 95.8804) -> (138.5366, 95.5909)
  line L31 (139.2596, 96.0792) -> (139.332, 95.8804)
  line L32 (138.8261, 94.7955) -> (139.6215, 95.085)
  line L33 (139.2238, 94.9403) -> (138.8261, 94.7955)
  line L34 (139.495, 94.8138) -> (139.2238, 94.9403)
  line L35 (139.7662, 94.6873) -> (139.495, 94.8138)
  line L36 (139.8386, 94.4885) -> (139.7662, 94.6873)
  line L37 (140.1281, 93.6932) -> (140.3452, 93.0967)
  line L38 (139.8569, 93.8196) -> (140.1281, 93.6932)
  line L39 (139.4592, 93.6749) -> (139.8569, 93.8196)
  line L40 (139.3327, 93.4037) -> (139.4592, 93.6749)
  line L41 (139.5498, 92.8072) -> (139.3327, 93.4037)
  line L42 (139.8393, 92.0118) -> (139.6946, 92.4095)
  line L43 (139.7669, 92.2107) -> (139.8393, 92.0118)
  line L44 (140.96, 92.6449) -> (139.7669, 92.2107)
  line L45 (140.8876, 92.8437) -> (140.96, 92.6449)
  line L46 (140.1288, 91.2165) -> (140.2735, 90.8188)
  line L47 (140.2553, 91.4877) -> (140.1288, 91.2165)
  line L48 (140.6529, 91.6324) -> (140.2553, 91.4877)
  line L49 (140.9242, 91.506) -> (140.6529, 91.6324)
  line L50 (141.0689, 91.1083) -> (140.9242, 91.506)
  line L51 (140.9424, 90.8371) -> (141.0689, 91.1083)
  line L52 (140.7436, 90.7647) -> (140.9424, 90.8371)
  line L53 (140.4541, 91.5601) -> (140.7436, 90.7647)
  line L54 (140.9249, 89.0293) -> (142.1179, 89.4635)
  line L55 (141.2144, 88.2339) -> (140.9249, 89.0293)
  line L56 (142.5521, 88.2705) -> (142.8416, 87.4751)
  line L57 (141.3591, 87.8362) -> (142.5521, 88.2705)
  line L58 (141.6486, 87.0409) -> (141.3591, 87.8362)
  line L59 (142.1004, 87.6557) -> (141.9556, 88.0534)
  line L60 (141.7933, 86.6432) -> (142.9864, 87.0774)
  line L61 (142.0104, 86.0467) -> (141.7933, 86.6432)
  line L62 (142.2816, 85.9202) -> (142.0104, 86.0467)
  line L63 (143.077, 86.2097) -> (142.2816, 85.9202)
  line L64 (143.2035, 86.4809) -> (143.077, 86.2097)
  line L65 (142.9864, 87.0774) -> (143.2035, 86.4809)
  line L66 (143.6377, 85.2879) -> (143.5112, 85.0167)
  line L67 (143.4929, 85.6856) -> (143.6377, 85.2879)
  line L68 (143.2217, 85.812) -> (143.4929, 85.6856)
  line L69 (143.0229, 85.7397) -> (143.2217, 85.812)
  line L70 (142.8964, 85.4685) -> (143.0229, 85.7397)
  line L71 (143.0412, 85.0708) -> (142.8964, 85.4685)
  line L72 (142.9147, 84.7996) -> (143.0412, 85.0708)
  line L73 (142.7159, 84.7272) -> (142.9147, 84.7996)
  line L74 (142.4447, 84.8537) -> (142.7159, 84.7272)
  line L75 (142.2999, 85.2514) -> (142.4447, 84.8537)
  line L76 (142.4264, 85.5226) -> (142.2999, 85.2514)
  line L77 (141.254, 98.1847) -> (139.8224, 97.6636)
  line L78 (141.5145, 97.4688) -> (141.254, 98.1847)
  line L79 (141.3628, 97.1434) -> (141.5145, 97.4688)
  line L80 (140.8856, 96.9697) -> (141.3628, 97.1434)
  line L81 (140.5601, 97.1215) -> (140.8856, 96.9697)
  line L82 (140.2996, 97.8373) -> (140.5601, 97.1215)
  line L83 (140.5171, 95.7548) -> (140.3434, 96.232)
  line L84 (140.4303, 95.9934) -> (140.5171, 95.7548)
  line L85 (141.3847, 96.3407) -> (140.4303, 95.9934)
  line L86 (141.2978, 96.5793) -> (141.3847, 96.3407)
  line L87 (141.7321, 95.3863) -> (140.7777, 95.0389)
  line L88 (141.9926, 94.6705) -> (141.7321, 95.3863)
  line L89 (141.8408, 94.3451) -> (141.9926, 94.6705)
  line L90 (141.125, 94.0845) -> (141.8408, 94.3451)
  line L91 (141.2987, 93.6073) -> (142.7303, 94.1284)
  line L92 (141.5593, 92.8915) -> (141.2987, 93.6073)
  line L93 (141.8847, 92.7397) -> (141.5593, 92.8915)
  line L94 (142.1233, 92.8266) -> (141.8847, 92.7397)
  line L95 (142.3619, 92.9134) -> (142.1233, 92.8266)
  line L96 (142.5137, 93.2389) -> (142.3619, 92.9134)
  line L97 (142.2531, 93.9547) -> (142.5137, 93.2389)
  line L98 (143.0347, 91.8072) -> (142.8611, 92.2845)
  line L99 (142.883, 91.4818) -> (143.0347, 91.8072)
  line L100 (142.1672, 91.2213) -> (142.883, 91.4818)
  line L101 (141.9066, 91.9371) -> (142.1672, 91.2213)
  line L102 (142.0584, 92.2625) -> (141.9066, 91.9371)
  line L103 (142.3838, 92.1108) -> (142.0584, 92.2625)
  line L104 (142.6444, 91.395) -> (142.3838, 92.1108)
  line L105 (142.5146, 90.2668) -> (142.3409, 90.7441)
  line L106 (142.4277, 90.5055) -> (142.5146, 90.2668)
  line L107 (143.8593, 91.0265) -> (142.4277, 90.5055)
  line L108 (143.7725, 91.2651) -> (143.8593, 91.0265)
  line L109 (142.9488, 89.0738) -> (142.7751, 89.551)
  line L110 (142.8619, 89.3124) -> (142.9488, 89.0738)
  line L111 (144.2936, 89.8335) -> (142.8619, 89.3124)
  line L112 (144.2067, 90.0721) -> (144.2936, 89.8335)
  line L113 (143.3941, 98.5102) -> (143.2424, 98.1848)
  line L114 (143.2204, 98.9875) -> (143.3941, 98.5102)
  line L115 (142.895, 99.1392) -> (143.2204, 98.9875)
  line L116 (142.6564, 99.0524) -> (142.895, 99.1392)
  line L117 (142.5046, 98.7269) -> (142.6564, 99.0524)
  line L118 (142.6783, 98.2497) -> (142.5046, 98.7269)
  line L119 (142.5265, 97.9243) -> (142.6783, 98.2497)
  line L120 (142.2879, 97.8374) -> (142.5265, 97.9243)
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sketch "Target Cutout" plane through (0, 0, 0) normal (0, 0, 1) x axis (1, 0, 0)
  line L1 (62, -2) -> (47, -2)
  line L2 (47, -2) -> (47, 107)
  line L3 (62, 107) -> (62, -2)
  line L4 (47, 107) -> (62, 107)
  line L5 (29, 107) -> (29, -2)
  line L6 (47, 107) -> (29, 107)
  line L7 (29, -2) -> (47, -2)
  circle C1 centre (37, 32.5) radius 2
  circle C2 centre (37, 72.5) radius 2
  circle C3 centre (57, 3) radius 1.4
  circle C4 centre (37, 92.5) radius 2
  circle C5 centre (57, 3) radius 1.9
  circle C6 centre (37, 12.5) radius 2
  circle C7 centre (57, 77.5) radius 4
  circle C8 centre (57, 77.5) radius 1.9
  circle C9 centre (57, 3) radius 4
  circle C10 centre (57, 77.5) radius 1.4
  circle C11 centre (37, 52.5) radius 2
  concentric C3 C5
  concentric C7 C8
  perpendicular L2 L6
  perpendicular L5 L7
  dimension "d439" diameter C7 = 8
  dimension "d440" diameter C9 = 8
  dimension "d441" diameter C5 = 3.8
  dimension "d442" diameter C8 = 3.8
sketch "Kickers" plane through (0, 0, 0) normal (0, 0, 1) x axis (1, 0, 0)
  line L1 (-17.9996, 16.5424) -> (-17.9993, 16.9967)
  line L2 (-17.9995, 13.0183) -> (18.0005, 13.0189)
  line L3 (18.0004, 16.543) -> (-17.9996, 16.5424)
  line L4 (30, -4.4) -> (30, -17)
  line L5 (-26.4995, -16.9989) -> (-17.9995, -16.9987)
  line L6 (15.0006, -16.5331) -> (15, 16.543)
  line L7 (30, 4.5) -> (29.8333, 4.4)
  line L8 (-14.9977, 16.5424) -> (-14.9977, 16.5374)
  line L9 (25.9, -8.2) -> (25.9, -4.4)
  line L10 (-17.9995, -16.9987) -> (-17.999, -16.5011)
  line L11 (-26.5001, 16.9965) -> (-17.9993, 16.9967)
  line L12 (-17.999, -16.5011) -> (-17.9996, 16.9967)
  line L13 (18.001, -16.536) -> (-17.999, -16.5011)
  line L14 (-17.999, -16.5011) -> (-17.999, -16.5011)
  line L15 (-26.5001, 16.9965) -> (-26.4995, -16.9989)
  line L16 (18, -12.9962) -> (-17.999, -12.999)
  line L17 (18.001, 17.0002) -> (18.0004, -16.9998)
  line L18 (18.001, -12.9962) -> (18, -12.9962)
  line L19 (18.5, -4.4) -> (18.5, -8.2)
  line L20 (30, -4.4) -> (29.5, -4.4)
  line L21 (26.5, -4.3) -> (26.625, -4.4)
  line L22 (18.001, -16.9998) -> (18.0004, 16.543)
  line L23 (26.625, 4.4) -> (26.5, 4.3)
  line L24 (22.1, 4.4) -> (22.1, 8.4)
  line L25 (29, 17) -> (30, 17)
  line L26 (22.1, -8.2) -> (22.1, -4.4)
  line L27 (26.5, 4.3) -> (26.5, -4.3)
  line L28 (18.5, 4.4) -> (29.5, 4.4)
  line L29 (30, 17) -> (30, 4.4)
  line L30 (30, -17) -> (29, -17)
  line L31 (29.5, -8.2) -> (29.5, -4.4)
  line L32 (18.5, 8.4) -> (29.5, 8.4)
  line L33 (18.5, -4.4) -> (29.5, -4.4)
  line L34 (29.5, 4.4) -> (29.5, 8.4)
  line L35 (30, 4.4) -> (29.8333, 4.4)
  line L36 (-14.9983, -16.504) -> (-14.9977, 16.5374)
  line L37 (30, -4.5) -> (29.5, -4.4)
  line L38 (18.5, 8.4) -> (18.5, 4.4)
  line L39 (25.9, 4.2) -> (25.9, -4.4)
  line L40 (18.0004, -16.9998) -> (29, -17)
  line L41 (18.5, -8.2) -> (29.5, -8.2)
  line L42 (25.9, 4.2) -> (25.9, 8.4)
  line L43 (18.001, 17.0002) -> (29, 17)
  line L44 (18.5, 4.4) -> (29.8333, 4.4)
  circle C1 centre (-14.5, -7) radius 3.5
  circle C2 centre (-14.5, 7) radius 2.1
  circle C3 centre (-14.5, 7) radius 3.5
  circle C4 centre (-14.5, -7) radius 2.1
  circle C5 centre (21.5, 13.2) radius 2.1
  circle C6 centre (21.5, 13.2) radius 3.5
  circle C7 centre (21.5, -13.2) radius 2.1
  circle C8 centre (21.5, -13.2) radius 3.5
  point P48 (25.9, -4.4)
  point P30 (22.1, -4.4)
  point P57 (25.9, 8.4)
  point P34 (22.1, 8.4)
  point P53 (30, -4.5)
  point P52 (30, 4.5)
  point P19 (22.1, 4.4)
  point P50 (30, 4.4)
  point P15 (26.625, -4.4)
  point P13 (26.625, 4.4)
  point P64 (18.001, -16.9998)
  coincident P48 L33
  coincident P30 L33
  coincident P57 L32
  coincident P34 L32
  concentric C5 C6
  concentric C7 C8
  coincident P53 L4
  coincident P52 L4
  coincident P19 L44
  coincident P50 L4
  coincident P15 L33
  coincident P13 L44
  coincident L40 P64
  dimension "d447" diameter C7 = 4.2
  dimension "d448" diameter C5 = 4.2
